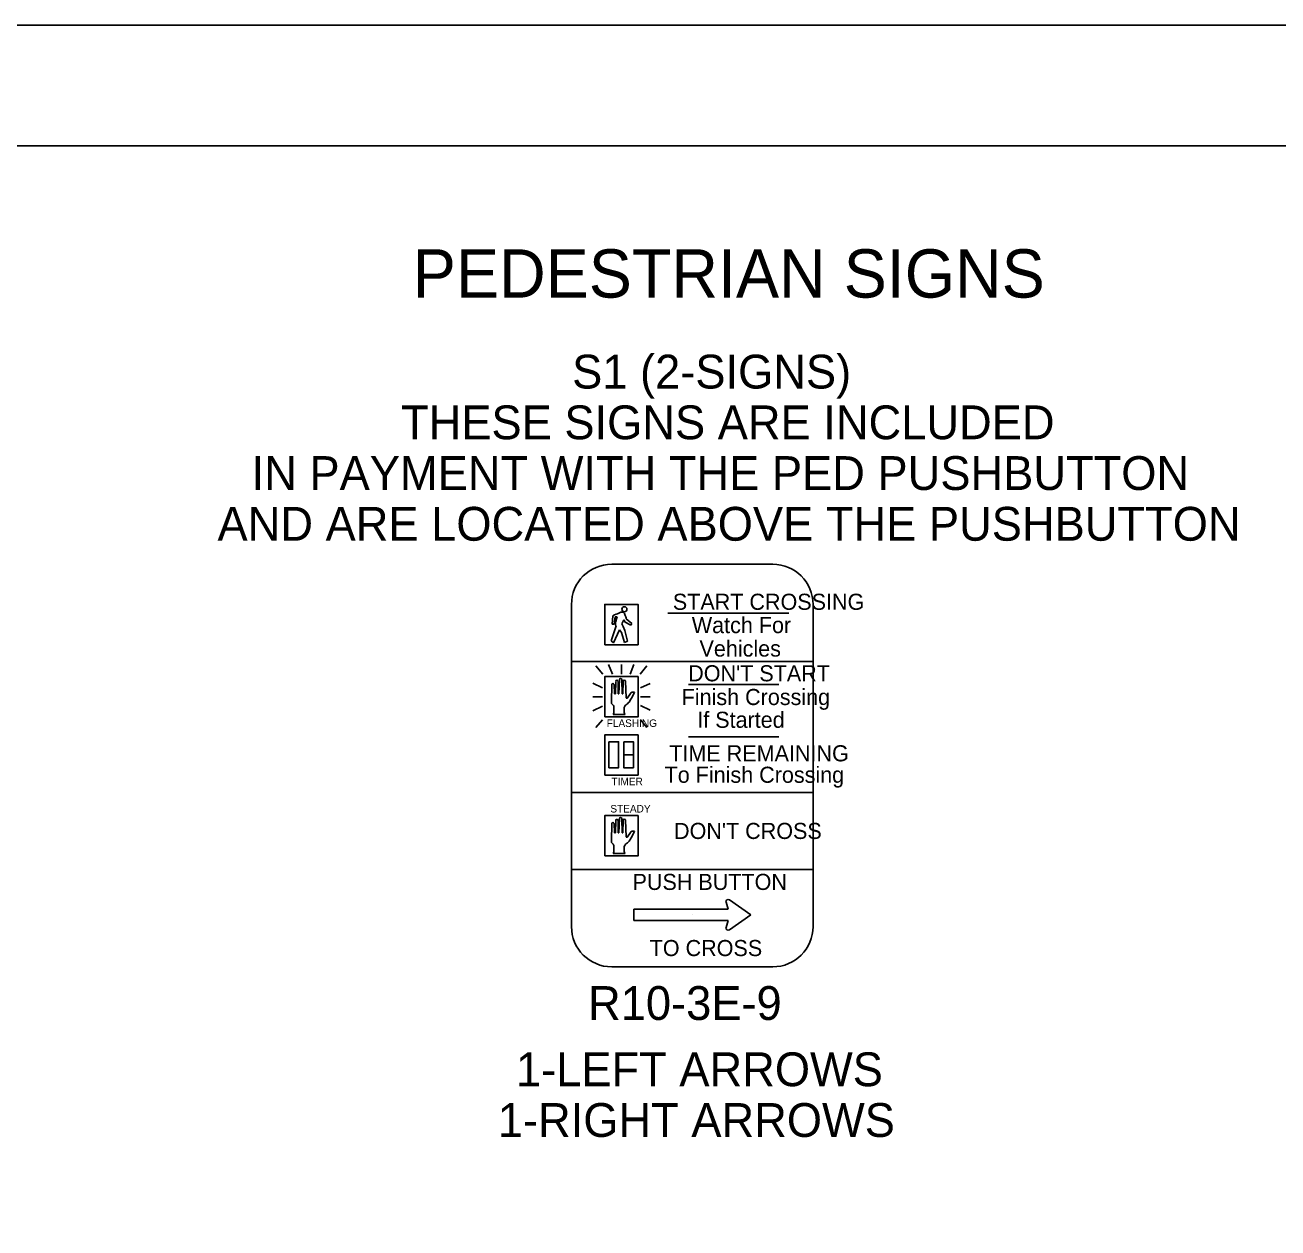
# Model space of a CAD drawing. Extents: x -32.9 to 34, y 0 to 22.3.
# Drawn here: x 5.18 to 10.37, y 17.02 to 22 of the extents above; entities that cross this region are included whole.
import ezdxf

# ---------------------------------------------------------------- set-up
doc = ezdxf.new("R2010")
doc.units = 0
for name, color, linetype in [('GE_P_Alignment', 7, 'Continuous'), ('PF_X_Ground_Line', 7, 'Continuous'), ('PV_P_Curb', 7, 'Continuous'), ('PV_P_Curb_Ramp', 7, 'Continuous')]:
    doc.layers.add(name, color=color, linetype=linetype)

msp = doc.modelspace()

# ---------------------------------------------------------------- linework, layer by layer
at = {"layer": 'GE_P_Alignment'}
msp.add_lwpolyline([(0, 0), (34, 0), (34, 22), (0, 22)], close=True, dxfattribs=at)
at = {"layer": 'PV_P_Curb'}
for p, q in [((7.617, 19.5546), (7.6144, 19.5194)), ((7.6224, 19.5201), (7.6266, 19.5496)), ((7.6266, 19.5496), (7.6354, 19.5501)), ((7.6354, 19.5501), (7.6302, 19.5336)), ((7.8448, 19.5659), (8.346, 19.5659)), ((7.6313, 19.5129), (7.6104, 19.4508)), ((7.6144, 19.5194), (7.6224, 19.5201)), ((7.6207, 19.4429), (7.6444, 19.4968)), ((7.6302, 19.5144), (7.6313, 19.5129)), ((7.6444, 19.4968), (7.6534, 19.4858)), ((7.6549, 19.5214), (7.6624, 19.5373)), ((7.6604, 19.5102), (7.6549, 19.5214)), ((7.6676, 19.4944), (7.6604, 19.5102)), ((7.6624, 19.5373), (7.6682, 19.5276)), ((7.6682, 19.5276), (7.6914, 19.5164)), ((7.6727, 19.5416), (7.6727, 19.5416)), ((7.6967, 19.5232), (7.6727, 19.5416)), ((7.6914, 19.5164), (7.6967, 19.5232)), ((7.6104, 19.4508), (7.6207, 19.4429)), ((7.6534, 19.4858), (7.6651, 19.4439)), ((7.6651, 19.4439), (7.6777, 19.4501)), ((7.6777, 19.4501), (7.6676, 19.4944)), ((7.4462, 19.3654), (8.4462, 19.3654)), ((7.5472, 19.3474), (7.5758, 19.3129)), ((7.5997, 19.3526), (7.6156, 19.3129)), ((7.6529, 19.3129), (7.6529, 19.3526)), ((7.6889, 19.3129), (7.7041, 19.3526)), ((7.7587, 19.3474), (7.7301, 19.3129)), ((7.6427, 19.2321), (7.6444, 19.2903)), ((7.6551, 19.2907), (7.6557, 19.2321)), ((7.574, 19.2567), (7.5343, 19.2752)), ((7.6117, 19.1974), (7.6134, 19.2703)), ((7.6227, 19.2703), (7.6247, 19.2321)), ((7.6279, 19.2321), (7.6294, 19.2832)), ((7.6391, 19.2832), (7.6394, 19.2321)), ((7.6593, 19.2321), (7.6601, 19.2831)), ((7.6696, 19.2834), (7.6722, 19.2149)), ((7.7318, 19.2558), (7.7714, 19.274)), ((7.9304, 19.2699), (8.3046, 19.2699)), ((7.574, 19.2196), (7.5343, 19.2196)), ((7.6247, 19.2321), (7.6279, 19.2321)), ((7.6394, 19.2321), (7.6427, 19.2321)), ((7.6557, 19.2321), (7.6593, 19.2321)), ((7.6782, 19.2146), (7.6901, 19.233)), ((7.7714, 19.2196), (7.7318, 19.2196)), ((7.574, 19.1808), (7.5343, 19.1612)), ((7.6679, 19.1462), (7.6189, 19.1462)), ((7.622, 19.1524), (7.622, 19.1768)), ((7.6646, 19.1751), (7.6646, 19.1539)), ((7.7318, 19.1826), (7.7714, 19.1639)), ((7.574, 19.1241), (7.5471, 19.0917)), ((7.7318, 19.1241), (7.7587, 19.0917)), ((7.9304, 19.053), (8.3046, 19.053)), ((7.6625, 18.9796), (7.7028, 18.9796)), ((7.4462, 18.8237), (8.4462, 18.8237)), ((7.6117, 18.6219), (7.6134, 18.6948)), ((7.6227, 18.6948), (7.6247, 18.6566)), ((7.6279, 18.6566), (7.6294, 18.7077)), ((7.6391, 18.7077), (7.6394, 18.6566)), ((7.6427, 18.6566), (7.6444, 18.7148)), ((7.6551, 18.7151), (7.6557, 18.6566)), ((7.6593, 18.6566), (7.6601, 18.7076)), ((7.6696, 18.7079), (7.6722, 18.6393)), ((7.6247, 18.6566), (7.6279, 18.6566)), ((7.6394, 18.6566), (7.6427, 18.6566)), ((7.6557, 18.6566), (7.6593, 18.6566)), ((7.6782, 18.639), (7.6901, 18.6574)), ((7.6679, 18.5707), (7.6189, 18.5707)), ((7.622, 18.5769), (7.622, 18.6012)), ((7.6646, 18.5996), (7.6646, 18.5783)), ((7.4462, 18.5043), (8.4462, 18.5043)), ((8.086, 18.3687), (8.095, 18.3402)), ((8.1884, 18.3168), (8.0999, 18.3789)), ((8.0947, 18.3402), (7.704, 18.3402)), ((7.704, 18.3402), (7.704, 18.2933)), ((7.9462, 18.3168), (7.9462, 18.3168)), ((8.095, 18.3402), (8.0947, 18.3402)), ((8.0999, 18.2546), (8.1884, 18.3168)), ((8.095, 18.2933), (8.086, 18.2649))]:
    msp.add_line(p, q, dxfattribs=at)
for points in [[(7.6129, 19.7682), (8.2795, 19.7682)], [(7.4462, 18.2682), (7.4462, 19.6015)], [(8.4462, 19.6015), (8.4462, 18.2682)], [(7.7071, 19.238), (7.6974, 19.2184), (7.6898, 19.2048)], [(7.7071, 18.6624), (7.6974, 18.6429), (7.6898, 18.6292)], [(7.704, 18.2933), (8.0947, 18.2933)], [(8.2795, 18.1015), (7.6129, 18.1015)]]:
    msp.add_lwpolyline(points, dxfattribs=at)
for points in [[(7.584, 19.4348), (7.7218, 19.4348), (7.7218, 19.6015), (7.584, 19.6015)], [(7.584, 19.1362), (7.7218, 19.1362), (7.7218, 19.3029), (7.584, 19.3029)], [(7.584, 18.895), (7.7218, 18.895), (7.7218, 19.0617), (7.584, 19.0617)], [(7.6009, 19.0335), (7.6412, 19.0335), (7.6412, 18.9256), (7.6009, 18.9256)], [(7.6625, 19.0335), (7.7028, 19.0335), (7.7028, 18.9256), (7.6625, 18.9256)], [(7.584, 18.5607), (7.7218, 18.5607), (7.7218, 18.7273), (7.584, 18.7273)]]:
    msp.add_lwpolyline(points, close=True, dxfattribs=at)
msp.add_circle((7.6653, 19.5816), 0.0103, dxfattribs=at)
for centre, radius, start, end in [((7.6129, 19.6015), 0.1667, 90, 180), ((8.2795, 19.6015), 0.1667, 0, 90), ((7.6497, 19.2892), 0.00538, 14.8098, 166.7635), ((7.6179, 19.2689), 0.00491, 17.2617, 162.7383), ((7.6341, 19.2827), 0.00492, 8.2338, 172.7854), ((7.6648, 19.2829), 0.00484, 7.5404, 176.7973), ((7.7002, 19.2269), 0.012, 86.7688, 149.658), ((7.7012, 19.2142), 0.0246, 76.4727, 90.8564), ((7.6229, 19.1967), 0.0115, 175.876, 235.3646), ((7.6059, 19.175), 0.0162, 6.5622, 49.5415), ((7.6899, 19.167), 0.0266, 117.1684, 162.5699), ((7.6752, 19.2162), 0.00319, 202.4359, 334.4764), ((7.6501, 19.2263), 0.0451, 307.7756, 331.4618), ((7.6117, 19.1543), 0.0104, 311.3432, 350.588), ((7.6754, 19.1542), 0.011, 181.2383, 225.3799), ((7.6497, 18.7136), 0.00538, 14.8098, 166.7635), ((7.6179, 18.6934), 0.00491, 17.2617, 162.7383), ((7.6341, 18.7071), 0.00492, 8.2338, 172.7854), ((7.6648, 18.7073), 0.00484, 7.5404, 176.7973), ((7.6229, 18.6212), 0.0115, 175.876, 235.3646), ((7.6899, 18.5914), 0.0266, 117.1684, 162.5699), ((7.6752, 18.6406), 0.00319, 202.4359, 334.4764), ((7.6501, 18.6507), 0.0451, 307.7756, 331.4618), ((7.7002, 18.6513), 0.012, 86.7688, 149.658), ((7.7012, 18.6387), 0.0246, 76.4727, 90.8564), ((7.6059, 18.5994), 0.0162, 6.5622, 49.5415), ((7.6117, 18.5787), 0.0104, 311.3432, 350.588), ((7.6754, 18.5787), 0.011, 181.2383, 225.3799), ((8.0947, 18.3715), 0.00912, 54.9207, 197.6378), ((7.6129, 18.2682), 0.1667, 180, 270), ((8.0947, 18.2621), 0.00912, 162.3622, 305.0792), ((8.2795, 18.2682), 0.1667, 270, 0)]:
    msp.add_arc(centre, radius, start, end, dxfattribs=at)
for points in [[(7.6604, 19.5693), (7.6601, 19.5693), (7.6578, 19.5699), (7.6547, 19.5699), (7.6528, 19.5699), (7.6504, 19.5698), (7.645, 19.5668), (7.6279, 19.5592), (7.617, 19.5546)], [(7.6354, 19.5501), (7.6334, 19.5443), (7.6317, 19.5384), (7.6296, 19.5305), (7.6283, 19.5249), (7.6276, 19.5194), (7.6291, 19.5164), (7.6302, 19.5144)], [(7.6727, 19.5416), (7.6718, 19.5488), (7.6687, 19.5558), (7.6659, 19.5641), (7.6617, 19.5683), (7.6604, 19.5693)]]:
    msp.add_open_spline(points, degree=3, dxfattribs=at)
at = {"layer": 'PV_P_Curb_Ramp'}
msp.add_lwpolyline([(1.5, 21.5), (33.5, 21.5), (33.5, 0.5), (1.5, 0.5)], close=True, dxfattribs=at)

# ---------------------------------------------------------------- texts
at = {"layer": 'PF_X_Ground_Line'}
for s, height, p in [('PEDESTRIAN SIGNS', 0.2, (6.7895, 20.8717)), ('S1 (2-SIGNS)', 0.14, (7.449, 20.4954)), ('THESE SIGNS ARE INCLUDED ', 0.14, (6.7407, 20.2854)), ('IN PAYMENT WITH THE PED PUSHBUTTON', 0.14, (6.1227, 20.0754)), ('AND ARE LOCATED ABOVE THE PUSHBUTTON', 0.14, (5.9814, 19.8654)), ('R10-3E-9', 0.14, (7.515, 17.8816)), ('1-LEFT ARROWS', 0.14, (7.2165, 17.6074)), ('1-RIGHT ARROWS', 0.14, (7.1414, 17.3974))]:
    msp.add_text(s, height=height, dxfattribs=at).set_placement(p)
at = {"layer": 'PV_P_Curb'}
for s, height, p in [('START CROSSING', 0.066667, (7.8657, 19.5793)), ('Watch For', 0.06667, (7.9442, 19.4828)), ('Vehicles', 0.06667, (7.9761, 19.3857)), ("DON'T START", 0.066667, (7.9293, 19.2833)), ('Finish Crossing', 0.066667, (7.9022, 19.1851)), ('If Started', 0.06667, (7.9668, 19.0908)), ('FLASHING', 0.03111, (7.5921, 19.0946)), ('TIME REMAINING', 0.066667, (7.851, 18.9521)), ('To Finish Crossing', 0.066667, (7.8316, 18.8632)), ('TIMER', 0.03111, (7.6119, 18.8533)), ('STEADY', 0.03111, (7.6072, 18.7403)), ("DON'T CROSS", 0.066667, (7.8707, 18.6307)), ('PUSH BUTTON', 0.066667, (7.699, 18.4197)), ('TO CROSS', 0.06667, (7.7699, 18.1459))]:
    msp.add_text(s, height=height, dxfattribs=at).set_placement(p)

doc.saveas('drawing.dxf')
